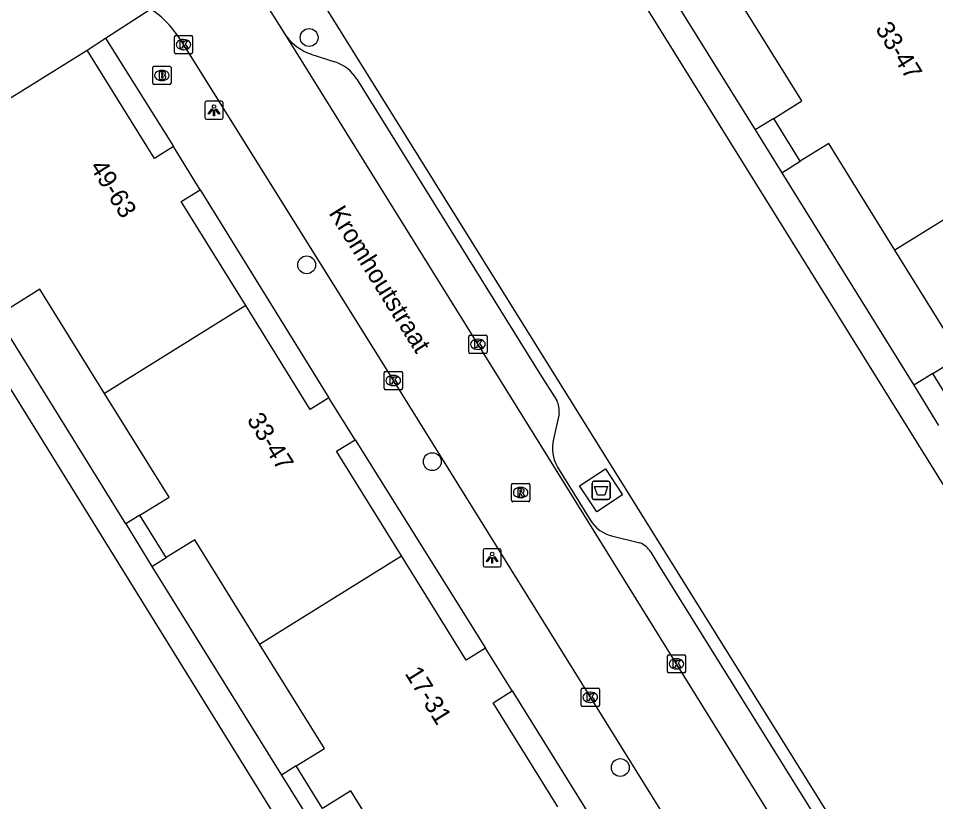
# Model space of a CAD drawing. Extents: x 160037 to 160839, y 385326 to 386441.
# Drawn here: x 160249.2 to 160299.5, y 386174.4 to 386217.3 of the extents above; entities that cross this region are included whole.
import ezdxf

# ---------------------------------------------------------------- set-up
doc = ezdxf.new("R2010")
doc.units = 0
for name, color, linetype in [('IMGEO_Afval_apart_plaats', 7, 'Continuous'), ('IMGEO_Boom', 7, 'Continuous'), ('IMGEO_Brandkraan', 7, 'Continuous'), ('IMGEO_Kolk', 7, 'Continuous'), ('IMGEO_Lichtpunt', 7, 'Continuous'), ('IMGEO_Openbare_ruimte_label', 7, 'Continuous'), ('IMGEO_Pand', 7, 'Continuous'), ('IMGEO_Pand_nummerreeks', 7, 'Continuous'), ('IMGEO_Rijbaan_lokaal_open', 7, 'Continuous'), ('IMGEO_Rioolput', 7, 'Continuous'), ('IMGEO_Voetpad_gesloten', 7, 'Continuous'), ('IMGEO_Voetpad_op_trap', 7, 'Continuous'), ('IMGEO_Voetpad_open', 7, 'Continuous')]:
    doc.layers.add(name, color=color, linetype=linetype)

msp = doc.modelspace()

# ---------------------------------------------------------------- linework, layer by layer
at = {"layer": 'IMGEO_Afval_apart_plaats'}
for p, q in [((160280.629, 386191.066), (160280.629, 386191.866)), ((160280.629, 386191.866), (160280.629, 386191.066)), ((160280.729, 386191.966), (160281.519, 386191.966)), ((160281.519, 386191.966), (160280.729, 386191.966)), ((160281.619, 386191.866), (160281.619, 386191.066)), ((160281.619, 386191.066), (160281.619, 386191.866)), ((160281.519, 386190.966), (160280.729, 386190.966)), ((160280.729, 386190.966), (160281.519, 386190.966))]:
    msp.add_line(p, q, dxfattribs=at)
msp.add_lwpolyline([(160280.772, 386191.68), (160281.476, 386191.68), (160281.327, 386191.21), (160280.921, 386191.21), (160280.772, 386191.68)], dxfattribs=at)
for centre, start, end in [((160280.729, 386191.866), 90, 180), ((160280.729, 386191.866), 90, 180), ((160281.519, 386191.866), 0, 90), ((160281.519, 386191.866), 360, 90), ((160280.729, 386191.066), 180, 270), ((160280.729, 386191.066), 180, 270), ((160281.519, 386191.066), 270, 0), ((160281.519, 386191.066), 270, 0)]:
    msp.add_arc(centre, 0.1, start, end, dxfattribs=at)
at = {"layer": 'IMGEO_Boom'}
for centre in [(160265.113, 386216.287), (160264.978, 386203.827), (160271.869, 386193.042), (160282.178, 386176.273)]:
    msp.add_circle(centre, 0.489, dxfattribs=at)
at = {"layer": 'IMGEO_Brandkraan'}
for p, q in [((160256.539, 386213.784), (160256.539, 386214.636)), ((160256.614, 386214.71), (160257.466, 386214.71)), ((160257.027, 386214.49), (160257.052, 386214.49)), ((160257.54, 386214.636), (160257.54, 386213.784)), ((160257.466, 386213.71), (160256.614, 386213.71)), ((160257.05, 386213.93), (160257.025, 386213.93))]:
    msp.add_line(p, q, dxfattribs=at)
for points in [[(160256.539, 386213.784), (160256.539, 386214.636)], [(160256.614, 386214.71), (160257.466, 386214.71)], [(160257.54, 386214.636), (160257.54, 386213.784)], [(160256.887, 386214.41), (160256.887, 386214.01), (160257.1, 386214.01)], [(160257.118, 386214.41), (160256.887, 386214.41)], [(160257.066, 386214.329), (160257.012, 386214.329), (160257.012, 386214.253)], [(160257.012, 386214.253), (160257.065, 386214.253)], [(160257.074, 386214.177), (160257.012, 386214.177), (160257.012, 386214.096)], [(160257.012, 386214.096), (160257.074, 386214.096)], [(160257.466, 386213.71), (160256.614, 386213.71)]]:
    msp.add_lwpolyline(points, dxfattribs=at)
for centre, radius, start, end in [((160256.616, 386214.634), 0.0765, 91.552, 178.448), ((160256.616, 386214.634), 0.0765, 91.552, 178.448), ((160257.464, 386214.634), 0.0765, 1.552, 88.448), ((160257.464, 386214.634), 0.0765, 1.552, 88.448), ((160257.067, 386214.291), 0.0379, 267.8285, 90.9355), ((160257.075, 386214.136), 0.0404, 269.8759, 90.5077), ((160257.106, 386214.261), 0.251, 268.6676, 293.5347), ((160257.122, 386214.265), 0.145, 59.4692, 91.5367), ((160257.147, 386214.312), 0.0922, 285.5137, 58.1501), ((160257.152, 386214.12), 0.105, 301.3115, 78.989), ((160256.616, 386213.786), 0.0765, 181.552, 268.448), ((160256.616, 386213.786), 0.0765, 181.552, 268.448), ((160257.464, 386213.786), 0.0765, 271.552, 358.448), ((160257.464, 386213.786), 0.0765, 271.552, 358.448)]:
    msp.add_arc(centre, radius, start, end, dxfattribs=at)
for centre, major_axis, ratio, start_param, end_param in [((160257.026, 386214.21), (-0.387, 0.002), 0.722429, 4.712389, 7.853982), ((160257.051, 386214.21), (-0.39, 0.002), 0.717154, 1.570796, 4.712389)]:
    msp.add_ellipse(centre, major_axis=major_axis, ratio=ratio, start_param=start_param, end_param=end_param, dxfattribs=at)
at = {"layer": 'IMGEO_Kolk'}
for p, q in [((160257.723, 386215.475), (160257.723, 386216.327)), ((160257.798, 386216.401), (160258.65, 386216.401)), ((160258.211, 386216.181), (160258.236, 386216.181)), ((160258.724, 386216.327), (160258.724, 386215.475)), ((160258.234, 386215.621), (160258.209, 386215.621)), ((160258.65, 386215.401), (160257.798, 386215.401)), ((160273.872, 386199.049), (160273.872, 386199.901)), ((160273.947, 386199.975), (160274.799, 386199.975)), ((160274.873, 386199.901), (160274.873, 386199.049)), ((160274.36, 386199.755), (160274.385, 386199.755)), ((160274.799, 386198.975), (160273.947, 386198.975)), ((160274.383, 386199.195), (160274.358, 386199.195)), ((160269.229, 386197.06), (160269.229, 386197.912)), ((160269.304, 386197.986), (160270.156, 386197.986)), ((160270.23, 386197.912), (160270.23, 386197.06)), ((160269.717, 386197.766), (160269.742, 386197.766)), ((160270.156, 386196.986), (160269.304, 386196.986)), ((160269.74, 386197.206), (160269.715, 386197.206)), ((160284.763, 386181.532), (160284.763, 386182.384)), ((160284.838, 386182.458), (160285.69, 386182.458)), ((160285.764, 386182.384), (160285.764, 386181.532)), ((160285.251, 386182.238), (160285.276, 386182.238)), ((160285.69, 386181.458), (160284.838, 386181.458)), ((160285.274, 386181.678), (160285.249, 386181.678)), ((160280.033, 386179.699), (160280.033, 386180.551)), ((160280.108, 386180.625), (160280.96, 386180.625)), ((160280.521, 386180.405), (160280.546, 386180.405)), ((160281.034, 386180.551), (160281.034, 386179.699)), ((160280.544, 386179.845), (160280.519, 386179.845)), ((160280.96, 386179.625), (160280.108, 386179.625))]:
    msp.add_line(p, q, dxfattribs=at)
for points in [[(160257.723, 386215.475), (160257.723, 386216.327)], [(160257.798, 386216.401), (160258.65, 386216.401)], [(160258.044, 386216.101), (160258.167, 386216.101), (160258.167, 386215.95), (160258.297, 386216.101), (160258.461, 386216.101), (160258.315, 386215.95), (160258.468, 386215.701), (160258.316, 386215.701), (160258.231, 386215.865), (160258.167, 386215.798), (160258.167, 386215.701), (160258.044, 386215.701), (160258.044, 386216.101)], [(160258.724, 386216.327), (160258.724, 386215.475)], [(160258.65, 386215.401), (160257.798, 386215.401)], [(160273.872, 386199.049), (160273.872, 386199.901)], [(160273.947, 386199.975), (160274.799, 386199.975)], [(160274.873, 386199.901), (160274.873, 386199.049)], [(160274.193, 386199.675), (160274.316, 386199.675), (160274.316, 386199.524), (160274.446, 386199.675), (160274.61, 386199.675), (160274.464, 386199.524), (160274.617, 386199.275), (160274.465, 386199.275), (160274.38, 386199.439), (160274.316, 386199.372), (160274.316, 386199.275), (160274.193, 386199.275), (160274.193, 386199.675)], [(160274.799, 386198.975), (160273.947, 386198.975)], [(160269.229, 386197.06), (160269.229, 386197.912)], [(160269.304, 386197.986), (160270.156, 386197.986)], [(160270.23, 386197.912), (160270.23, 386197.06)], [(160269.55, 386197.686), (160269.673, 386197.686), (160269.673, 386197.535), (160269.803, 386197.686), (160269.967, 386197.686), (160269.821, 386197.535), (160269.974, 386197.286), (160269.822, 386197.286), (160269.737, 386197.45), (160269.673, 386197.383), (160269.673, 386197.286), (160269.55, 386197.286), (160269.55, 386197.686)], [(160270.156, 386196.986), (160269.304, 386196.986)], [(160284.763, 386181.532), (160284.763, 386182.384)], [(160284.838, 386182.458), (160285.69, 386182.458)], [(160285.764, 386182.384), (160285.764, 386181.532)], [(160285.084, 386182.158), (160285.207, 386182.158), (160285.207, 386182.007), (160285.337, 386182.158), (160285.501, 386182.158), (160285.355, 386182.007), (160285.508, 386181.758), (160285.356, 386181.758), (160285.271, 386181.922), (160285.207, 386181.855), (160285.207, 386181.758), (160285.084, 386181.758), (160285.084, 386182.158)], [(160285.69, 386181.458), (160284.838, 386181.458)], [(160280.033, 386179.699), (160280.033, 386180.551)], [(160280.108, 386180.625), (160280.96, 386180.625)], [(160280.354, 386180.325), (160280.477, 386180.325), (160280.477, 386180.174), (160280.607, 386180.325), (160280.771, 386180.325), (160280.625, 386180.174), (160280.778, 386179.925), (160280.626, 386179.925), (160280.541, 386180.089), (160280.477, 386180.022), (160280.477, 386179.925), (160280.354, 386179.925), (160280.354, 386180.325)], [(160281.034, 386180.551), (160281.034, 386179.699)], [(160280.96, 386179.625), (160280.108, 386179.625)]]:
    msp.add_lwpolyline(points, dxfattribs=at)
for centre, start, end in [((160257.8, 386216.325), 91.552, 178.448), ((160257.8, 386216.325), 91.552, 178.448), ((160258.648, 386216.325), 1.552, 88.448), ((160258.648, 386216.325), 1.552, 88.448), ((160257.8, 386215.477), 181.552, 268.448), ((160257.8, 386215.477), 181.552, 268.448), ((160258.648, 386215.477), 271.552, 358.448), ((160258.648, 386215.477), 271.552, 358.448), ((160273.949, 386199.899), 91.552, 178.448), ((160273.949, 386199.899), 91.552, 178.448), ((160274.797, 386199.899), 1.552, 88.448), ((160274.797, 386199.899), 1.552, 88.448), ((160273.949, 386199.051), 181.552, 268.448), ((160273.949, 386199.051), 181.552, 268.448), ((160274.797, 386199.051), 271.552, 358.448), ((160274.797, 386199.051), 271.552, 358.448), ((160269.306, 386197.91), 91.552, 178.448), ((160269.306, 386197.91), 91.552, 178.448), ((160270.154, 386197.91), 1.552, 88.448), ((160270.154, 386197.91), 1.552, 88.448), ((160269.306, 386197.062), 181.552, 268.448), ((160269.306, 386197.062), 181.552, 268.448), ((160270.154, 386197.062), 271.552, 358.448), ((160270.154, 386197.062), 271.552, 358.448), ((160284.84, 386182.382), 91.552, 178.448), ((160284.84, 386182.382), 91.552, 178.448), ((160285.688, 386182.382), 1.552, 88.448), ((160285.688, 386182.382), 1.552, 88.448), ((160284.84, 386181.534), 181.552, 268.448), ((160284.84, 386181.534), 181.552, 268.448), ((160285.688, 386181.534), 271.552, 358.448), ((160285.688, 386181.534), 271.552, 358.448), ((160280.11, 386180.549), 91.552, 178.448), ((160280.11, 386180.549), 91.552, 178.448), ((160280.958, 386180.549), 1.552, 88.448), ((160280.958, 386180.549), 1.552, 88.448), ((160280.11, 386179.701), 181.552, 268.448), ((160280.11, 386179.701), 181.552, 268.448), ((160280.958, 386179.701), 271.552, 358.448), ((160280.958, 386179.701), 271.552, 358.448)]:
    msp.add_arc(centre, 0.0765, start, end, dxfattribs=at)
for centre, major_axis, ratio, start_param, end_param in [((160258.21, 386215.901), (-0.387, 0.002), 0.722429, 4.712389, 7.853982), ((160258.235, 386215.901), (-0.39, 0.002), 0.717154, 1.570796, 4.712389), ((160274.359, 386199.475), (-0.387, 0.002), 0.722429, 4.712389, 7.853982), ((160274.384, 386199.475), (-0.39, 0.002), 0.717154, 1.570796, 4.712389), ((160269.716, 386197.486), (-0.387, 0.002), 0.722429, 4.712389, 7.853982), ((160269.741, 386197.486), (-0.39, 0.002), 0.717154, 1.570796, 4.712389), ((160285.25, 386181.958), (-0.387, 0.002), 0.722429, 4.712389, 7.853982), ((160285.275, 386181.958), (-0.39, 0.002), 0.717154, 1.570796, 4.712389), ((160280.52, 386180.125), (-0.387, 0.002), 0.722429, 4.712389, 7.853982), ((160280.545, 386180.125), (-0.39, 0.002), 0.717154, 1.570796, 4.712389)]:
    msp.add_ellipse(centre, major_axis=major_axis, ratio=ratio, start_param=start_param, end_param=end_param, dxfattribs=at)
at = {"layer": 'IMGEO_Lichtpunt'}
for p, q in [((160259.397, 386212.71), (160259.397, 386211.903)), ((160259.397, 386212.71), (160259.397, 386211.903)), ((160260.299, 386212.805), (160259.491, 386212.805)), ((160260.299, 386212.805), (160259.491, 386212.805)), ((160260.393, 386211.903), (160260.393, 386212.71)), ((160260.393, 386211.903), (160260.393, 386212.71)), ((160259.491, 386211.809), (160260.299, 386211.809)), ((160259.491, 386211.809), (160260.299, 386211.809)), ((160274.653, 386188.174), (160274.653, 386187.367)), ((160274.653, 386188.174), (160274.653, 386187.367)), ((160275.555, 386188.269), (160274.747, 386188.269)), ((160275.555, 386188.269), (160274.747, 386188.269)), ((160275.649, 386187.367), (160275.649, 386188.174)), ((160275.649, 386187.367), (160275.649, 386188.174)), ((160274.747, 386187.273), (160275.555, 386187.273)), ((160274.747, 386187.273), (160275.555, 386187.273))]:
    msp.add_line(p, q, dxfattribs=at)
for points in [[(160259.771, 386212.374), (160259.81, 386212.346), (160259.622, 386212.084), (160259.584, 386212.111), (160259.771, 386212.374)], [(160259.873, 386212.326), (160259.92, 386212.326), (160259.92, 386212.004), (160259.873, 386212.004), (160259.873, 386212.326)], [(160259.983, 386212.346), (160260.021, 386212.373), (160260.208, 386212.111), (160260.169, 386212.083), (160259.983, 386212.346)], [(160275.027, 386187.838), (160275.066, 386187.81), (160274.878, 386187.548), (160274.84, 386187.575), (160275.027, 386187.838)], [(160275.239, 386187.81), (160275.277, 386187.837), (160275.464, 386187.575), (160275.425, 386187.547), (160275.239, 386187.81)], [(160275.129, 386187.79), (160275.176, 386187.79), (160275.176, 386187.468), (160275.129, 386187.468), (160275.129, 386187.79)]]:
    msp.add_lwpolyline(points, dxfattribs=at)
for centre in [(160259.896, 386212.508), (160275.152, 386187.972)]:
    msp.add_circle(centre, 0.0994, dxfattribs=at)
for centre, start, end in [((160259.491, 386212.71), 90, 180), ((160259.491, 386212.71), 90, 180), ((160260.299, 386212.71), 0, 90), ((160260.299, 386212.71), 0, 90), ((160259.491, 386211.903), 180, 270), ((160259.491, 386211.903), 180, 270), ((160260.299, 386211.903), 270, 0), ((160260.299, 386211.903), 270, 360), ((160274.747, 386188.174), 90, 180), ((160274.747, 386188.174), 90, 180), ((160275.555, 386188.174), 0, 90), ((160275.555, 386188.174), 0, 90), ((160274.747, 386187.367), 180, 270), ((160274.747, 386187.367), 180, 270), ((160275.555, 386187.367), 270, 0), ((160275.555, 386187.367), 270, 360)]:
    msp.add_arc(centre, 0.0946, start, end, dxfattribs=at)
at = {"layer": 'IMGEO_Pand'}
for points in [[(160290.591, 386211.858), (160292.134, 386212.815), (160288.633, 386218.457)], [(160245.235, 386210.809), (160252.944, 386215.602)], [(160257.675, 386210.306), (160256.637, 386209.661), (160252.944, 386215.602)], [(160292.05, 386209.507), (160290.591, 386211.858)], [(160297.243, 386204.638), (160293.617, 386210.48), (160292.05, 386209.507)], [(160259.144, 386207.945), (160257.675, 386210.306)], [(160304.668, 386209.246), (160297.243, 386204.638)], [(160261.637, 386201.596), (160258.095, 386207.293), (160259.144, 386207.945)], [(160299.312, 386197.878), (160300.847, 386198.83), (160297.243, 386204.638)], [(160253.899, 386196.785), (160250.352, 386202.489), (160248.725, 386201.477)], [(160261.637, 386201.596), (160253.899, 386196.785)], [(160266.201, 386196.535), (160265.179, 386195.899), (160261.637, 386201.596)], [(160300.679, 386195.676), (160299.312, 386197.878)], [(160255.83, 386190.106), (160257.432, 386191.102), (160253.899, 386196.785)], [(160267.63, 386194.236), (160266.201, 386196.535)], [(160270.177, 386187.887), (160266.62, 386193.608), (160267.63, 386194.236)], [(160257.275, 386187.783), (160255.83, 386190.106)], [(160262.387, 386183.044), (160258.837, 386188.755), (160257.275, 386187.783)], [(160262.387, 386183.044), (160270.177, 386187.887)], [(160274.789, 386182.823), (160273.734, 386182.167), (160270.177, 386187.887)], [(160264.411, 386176.36), (160265.949, 386177.316), (160262.387, 386183.044)], [(160276.249, 386180.473), (160274.789, 386182.823)], [(160278.755, 386174.128), (160275.211, 386179.827), (160276.249, 386180.473)], [(160265.856, 386174.037), (160264.411, 386176.36)], [(160270.948, 386169.274), (160267.392, 386174.992), (160265.856, 386174.037)]]:
    msp.add_lwpolyline(points, dxfattribs=at)
at = {"layer": 'IMGEO_Rijbaan_lokaal_open'}
for points in [[(160263.893, 386216.331), (160262.366, 386218.765)], [(160258.086, 386216.124), (160270.201, 386196.734), (160291.687, 386162.201)], [(160294.482, 386167.133), (160277.87, 386193.854), (160263.893, 386216.331)]]:
    msp.add_lwpolyline(points, dxfattribs=at)
msp.add_arc((160253.04, 386212.973), 5.949, 31.9794, 55.328, dxfattribs=at)
at = {"layer": 'IMGEO_Rioolput'}
for p, q in [((160276.289, 386191.848), (160277.141, 386191.848)), ((160276.214, 386190.922), (160276.214, 386191.774)), ((160276.702, 386191.628), (160276.727, 386191.628)), ((160277.215, 386191.774), (160277.215, 386190.922)), ((160277.141, 386190.848), (160276.289, 386190.848)), ((160276.725, 386191.068), (160276.7, 386191.068))]:
    msp.add_line(p, q, dxfattribs=at)
for points in [[(160276.289, 386191.848), (160277.141, 386191.848)], [(160276.214, 386190.922), (160276.214, 386191.774)], [(160276.803, 386191.546), (160276.551, 386191.548), (160276.551, 386191.148)], [(160276.729, 386191.467), (160276.675, 386191.467), (160276.675, 386191.386)], [(160276.675, 386191.386), (160276.727, 386191.386)], [(160277.215, 386191.774), (160277.215, 386190.922)], [(160277.141, 386190.848), (160276.289, 386190.848)], [(160276.551, 386191.148), (160276.675, 386191.148), (160276.675, 386191.31), (160276.686, 386191.31)], [(160276.733, 386191.281), (160276.804, 386191.148), (160276.944, 386191.148), (160276.879, 386191.274)]]:
    msp.add_lwpolyline(points, dxfattribs=at)
for centre, radius, start, end in [((160276.291, 386191.772), 0.0765, 91.552, 178.448), ((160276.291, 386191.772), 0.0765, 91.552, 178.448), ((160277.139, 386191.772), 0.0765, 1.552, 88.448), ((160277.139, 386191.772), 0.0765, 1.552, 88.448), ((160276.711, 386191.575), 0.19, 274.7715, 282.9687), ((160276.735, 386191.371), 0.0964, 77.0061, 93.1865), ((160276.749, 386191.428), 0.0378, 276.6634, 79.6772), ((160276.802, 386191.436), 0.109, 350.3612, 89.416), ((160276.8, 386191.436), 0.112, 277.5842, 350.9817), ((160276.784, 386191.221), 0.108, 29.5134, 73.7905), ((160276.291, 386190.924), 0.0765, 181.552, 268.448), ((160276.291, 386190.924), 0.0765, 181.552, 268.448), ((160276.685, 386191.257), 0.0533, 26.0293, 88.6989), ((160277.139, 386190.924), 0.0765, 271.552, 358.448), ((160277.139, 386190.924), 0.0765, 271.552, 358.448)]:
    msp.add_arc(centre, radius, start, end, dxfattribs=at)
for centre, major_axis, ratio, start_param, end_param in [((160276.701, 386191.348), (-0.387, 0.002), 0.722429, 4.712389, 7.853982), ((160276.726, 386191.348), (-0.39, 0.002), 0.717154, 1.570796, 4.712389)]:
    msp.add_ellipse(centre, major_axis=major_axis, ratio=ratio, start_param=start_param, end_param=end_param, dxfattribs=at)
at = {"layer": 'IMGEO_Voetpad_gesloten'}
msp.add_lwpolyline([(160282.305, 386191.224), (160280.889, 386190.284), (160279.943, 386191.709), (160281.359, 386192.649), (160282.305, 386191.224)], dxfattribs=at)
at = {"layer": 'IMGEO_Voetpad_op_trap'}
for points in [[(160290.591, 386211.858), (160289.571, 386211.224)], [(160291.031, 386208.874), (160292.05, 386209.507)], [(160299.312, 386197.878), (160298.269, 386197.229)], [(160255.83, 386190.106), (160255.053, 386189.624)], [(160256.495, 386187.299), (160257.275, 386187.783)], [(160264.411, 386176.36), (160263.593, 386175.853)]]:
    msp.add_lwpolyline(points, dxfattribs=at)
at = {"layer": 'IMGEO_Voetpad_open'}
for points in [[(160275.723, 386230.616), (160312.412, 386171.653)], [(160282.479, 386222.634), (160289.571, 386211.224)], [(160298.791, 386165.396), (160264.103, 386221.042)], [(160253.948, 386216.255), (160256.424, 386217.866)], [(160252.944, 386215.602), (160253.948, 386216.255)], [(160253.948, 386216.255), (160257.675, 386210.306)], [(160265.209, 386215.385), (160266.528, 386214.95)], [(160267.733, 386214.002), (160277.76, 386197.862), (160278.693, 386196.397)], [(160289.571, 386211.224), (160291.031, 386208.874)], [(160241.195, 386209.143), (160277.737, 386150.227)], [(160291.031, 386208.874), (160298.269, 386197.229)], [(160259.144, 386207.945), (160266.201, 386196.535)], [(160255.053, 386189.624), (160247.986, 386201.019)], [(160298.269, 386197.229), (160299.637, 386195.028)], [(160278.825, 386195.665), (160278.508, 386194.271)], [(160267.63, 386194.236), (160274.789, 386182.823)], [(160278.742, 386192.744), (160280.531, 386189.856)], [(160255.053, 386189.624), (160256.495, 386187.299)], [(160281.766, 386188.959), (160283.243, 386188.584)], [(160283.846, 386188.079), (160284.291, 386187.352), (160293.488, 386172.587), (160294.051, 386171.395)], [(160256.495, 386187.299), (160263.593, 386175.853)], [(160276.249, 386180.473), (160283.335, 386169.074)], [(160263.593, 386175.853), (160265.035, 386173.528)]]:
    msp.add_lwpolyline(points, dxfattribs=at)
for centre, radius, start, end in [((160266.053, 386217.947), 2.697, 216.8047, 251.7748), ((160265.826, 386212.818), 2.245, 31.8412, 71.773), ((160277.495, 386195.803), 1.337, 354.0698, 26.3745), ((160280.576, 386193.806), 2.12, 167.3413, 210.0834), ((160282.159, 386190.799), 1.882, 210.0819, 257.9351), ((160282.868, 386187.524), 1.125, 29.5878, 70.5213)]:
    msp.add_arc(centre, radius, start, end, dxfattribs=at)

# ---------------------------------------------------------------- texts
at = {"layer": 'IMGEO_Openbare_ruimte_label'}
msp.add_text('Kromhoutstraat', height=1, rotation=301.9265, dxfattribs=at).set_placement((160266.163, 386206.668))
at = {"layer": 'IMGEO_Pand_nummerreeks'}
for s, rotation, p in [('33-47', 301.8202, (160296.141, 386216.767)), ('49-63', 301.8263, (160253.056, 386209.202)), ('33-47', 301.9217, (160261.671, 386195.338)), ('17-31', 301.9389, (160270.336, 386181.432))]:
    msp.add_text(s, height=1, rotation=rotation, dxfattribs=at).set_placement(p)

doc.saveas('drawing.dxf')
